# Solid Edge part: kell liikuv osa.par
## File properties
Title: kell liikuv osa
Author: Stella-Marii
Template: iso metric part.par
Last saved by: Stella-Marii
Revision: 6
Application: Solid Edge
Document Number: 16
Density: 7833,000 kg/m^3
Accuracy: 0,990
Username: Stella-Marii
Material: Steel, structural
Face Style: Steel
Fill Style: ANSI32(Steel)
Virtual Style: Brushed steel
Grouping: Metals\Steel
LibraryName: Materials
Coef. of Thermal Exp: 1.3e-05
Thermal Conductivity: 32.0
Specific Heat: 481.0
Modulus of Elasticity: 199947953000.0
Poisson's Ratio: 0.29
Yield Stress: 262000766.0
Ultimate Stress: 358527364.0
Elongation: 0.0
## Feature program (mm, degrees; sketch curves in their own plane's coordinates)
sketch for "unnamed RevolvedProtrusion 1" plane through (0, 0, 0) normal (1, 0, 0) x-axis (0, 1, 0)
  line (12.5, 0) -> (22.7759, 0)
  line (22.7759, 0) -> (24.9603, 3.0786)
  line (24.9603, 3.0786) -> (21.5126, 6.342)
  line (21.5126, 6.342) -> (19.02, 20.1533)
  line (19.02, 20.1533) -> (12.5, 20.1533)
  line (12.5, 20.1533) -> (12.5, 0)
revolve "unnamed RevolvedProtrusion 1" add full turn 360 deg
fillet "unnamed Round 1"
fillet "Round_2" radius 2
swept cutout "SweptCutout_2"
pattern "unnamed Pattern 1" of "SweptCutout_2"
pattern "Pattern_1" along a curve  XDirCount = 17; XDirSpacing = 7 mm
sketch used by "ExtrudedProtrusion_1" plane through (0, 0, 0) normal (0, 0, -1) x-axis (1, 0, 0)
extrude "ExtrudedProtrusion_1" add finite 8 along +normal
sketch for "ExtrudedCutout_2" plane through (17.6357, 0.25, -4) normal (0, 1, 0) x-axis (1, 0, 0)
extrude "ExtrudedCutout_2" cut finite 5.4848 symmetric
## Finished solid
Body 1: solid body, 38 faces, 94 edges, 58 vertices.
  Faces by surface: spline 17, plane 11, cylinder 5, cone 3, torus 2
  Edges by curve: circle 37, line 28, intersection 17, curve on surface 12
Bounding box of the edges (mm; curved faces can reach further): 47.911 x 47.911 x 28.153, from (-23.9554, -23.9554, -8) to (23.9554, 23.9554, 20.1533).
Cylindrical faces by radius (mm): R0.3218 x2, R1.929 x1, R2.0365 x1, R12.5 x1
Conical faces (half-angle, radius in mm at the cone's reference point): 10.2304 deg R21.5126 x1, 35.3575 deg R22.7759 x1, 46.5724 deg R24.9603 x1
Toroidal faces (ring radius, tube radius in mm): R22.3243 r2 x1, R23.3642 r2 x1
Planar faces by outward normal: +x 2, +y 1, +z 1, -x 2, -y 1, -z 2, oblique 2
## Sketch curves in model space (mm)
circle centre (0, 0, 0) radius 22.7759
circle centre (0, 0, 0) radius 12.5
line (0, -19.6326, 20.1533) -> (0, -23.3148, 7.6582)
circle centre (0, -19.6326, 20.1533) radius 1.9579
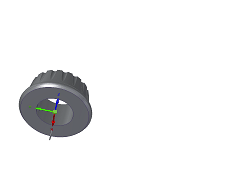
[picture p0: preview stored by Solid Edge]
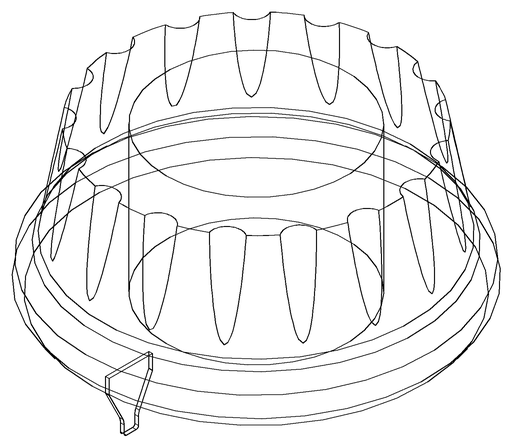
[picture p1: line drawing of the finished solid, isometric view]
